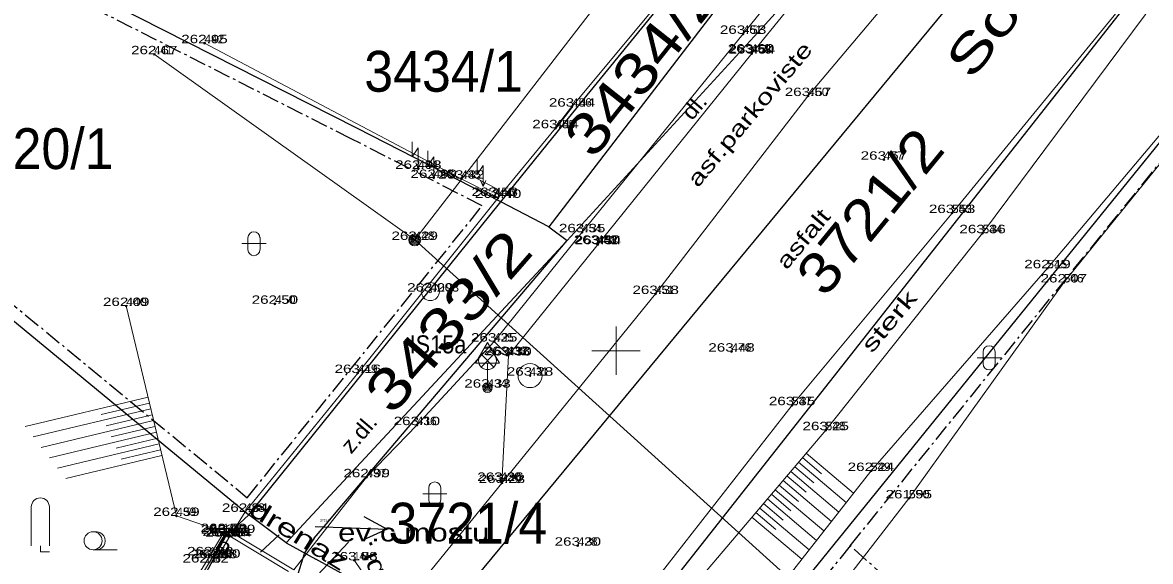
# Model space of a CAD drawing. Extents: x -568530 to -568223, y -1154101 to -1153740.
# Drawn here: x -568424.7 to -568377.75, y -1153908.77 to -1153886.34 of the extents above; entities that cross this region are included whole.
import ezdxf
from ezdxf.enums import TextEntityAlignment as Align

# ---------------------------------------------------------------- set-up
doc = ezdxf.new("R2010")
doc.units = 0
doc.header["$LTSCALE"] = 0.14
doc.header["$PDMODE"] = 32
doc.header["$PDSIZE"] = 0.07
doc.linetypes.add('DOT_DASHED', pattern=[7.7, 5, -1.2, 0.3, -1.2])
for name, color, linetype, lineweight in [('1', 7, 'Continuous', 25), ('10', 7, 'Continuous', 13), ('11', 7, 'Continuous', 13), ('12', 7, 'Continuous', 13), ('14', 7, 'Continuous', 13), ('15', 7, 'Continuous', 13), ('21', 7, 'Continuous', 13), ('22', 7, 'Continuous', 13), ('23', 7, 'Continuous', 13), ('24', 7, 'Continuous', 13), ('25', 7, 'Continuous', 13), ('27', 7, 'Continuous', 13), ('33', 7, 'Continuous', 13), ('34', 7, 'Continuous', 13), ('36', 7, 'Continuous', 13), ('4', 7, 'Continuous', 25), ('42', 7, 'Continuous', 13), ('51', 7, 'Continuous', 13), ('6', 7, 'DOT_DASHED', 25), ('61', 7, 'Continuous', 13), ('7', 7, 'Continuous', 13), ('8', 7, 'Continuous', 35), ('9', 7, 'Continuous', 13)]:
    doc.layers.add(name, color=color, linetype=linetype, lineweight=lineweight)
for name, color, linetype in [('13', 7, 'Continuous'), ('18', 7, 'Continuous'), ('19', 7, 'Continuous'), ('20', 7, 'Continuous'), ('40', 7, 'Continuous'), ('49', 7, 'Continuous')]:
    doc.layers.add(name, color=color, linetype=linetype)

msp = doc.modelspace()

# ---------------------------------------------------------------- linework, layer by layer
at = {"layer": '1'}
for p, q in [((-568432.8, -1153892.39), (-568415.28, -1153906.83)), ((-568402.8, -1153894.84), (-568402.04, -1153895.41)), ((-568413.73, -1153908), (-568402.04, -1153895.41)), ((-568413.73, -1153908), (-568412.5, -1153908.68))]:
    msp.add_line(p, q, dxfattribs=at)
for points in [[(-568412.56, -1153907.8), (-568411.98, -1153907.12), (-568411.65, -1153906.73), (-568402.04, -1153895.41), (-568393.94, -1153886.59), (-568382.28, -1153873.78), (-568334.11, -1153813.06), (-568281.93, -1153748.16)], [(-568397.85, -1153916.62), (-568348.36, -1153855.52), (-568306.73, -1153803.52), (-568266.23, -1153754.08)], [(-568404.79, -1153893.8), (-568410.79, -1153890.73), (-568424.86, -1153883.59), (-568440.41, -1153875.53), (-568467.48, -1153868.69)], [(-568413.73, -1153908), (-568415.28, -1153906.83), (-568404.79, -1153893.8), (-568402.87, -1153891.42), (-568401.2, -1153889.36), (-568395.23, -1153882.04), (-568393.86, -1153883.19), (-568402.8, -1153894.84), (-568404.79, -1153893.8)], [(-568415.28, -1153906.83), (-568416.25, -1153907.73), (-568417.28, -1153909.65), (-568429.7, -1153929.89), (-568430.98, -1153931.64), (-568432.38, -1153933.77), (-568434.43, -1153934.79), (-568436.25, -1153936.74), (-568450.95, -1153952.46)], [(-568412.56, -1153907.8), (-568412.97, -1153908.42), (-568413.31, -1153909.52)], [(-568397.85, -1153916.62), (-568398.69, -1153916.13), (-568401.59, -1153914.63), (-568407.5, -1153911.44), (-568412.5, -1153908.68)]]:
    msp.add_lwpolyline(points, dxfattribs=at)
at = {"layer": '10'}
msp.add_line((-568410.89, -1153908.73), (-568410.6, -1153909.16), dxfattribs=at)
for points in [[(-568341.41, -1153838.94), (-568349.83, -1153849.41), (-568360.25, -1153862.43), (-568369.78, -1153874.42), (-568378.19, -1153884.73), (-568386.01, -1153894.27), (-568392.67, -1153902.27), (-568398.22, -1153909.37), (-568401.79, -1153914.15), (-568403.6, -1153916.28)], [(-568384.23, -1153880.16), (-568392.01, -1153889.4), (-568398.35, -1153897.64), (-568404.75, -1153905.51), (-568410.43, -1153912.49)]]:
    msp.add_lwpolyline(points, dxfattribs=at)
at = {"layer": '11'}
for p, q in [((-568404.48, -1153900.2), (-568405.07, -1153899.62)), ((-568413.418, -1153909.12), (-568410.38, -1153905.27)), ((-568415.98, -1153907.59), (-568415.44, -1153906.71)), ((-568416.33, -1153907.55), (-568416.08, -1153907.72)), ((-568416.08, -1153907.72), (-568415.98, -1153907.59)), ((-568416.08, -1153907.72), (-568413.64, -1153909.2)), ((-568415.98, -1153907.59), (-568413.418, -1153909.12))]:
    msp.add_line(p, q, dxfattribs=at)
for points in [[(-568381.7, -1153869.78), (-568383.21, -1153872.58), (-568387.5, -1153877.91), (-568389.32, -1153880.18), (-568394.71, -1153886.81), (-568401.41, -1153895.07), (-568405.07, -1153899.62), (-568408.29, -1153903.1), (-568410.38, -1153905.27)], [(-568384.23, -1153880.16), (-568388.74, -1153880.73), (-568394.35, -1153887.63), (-568400.75, -1153895.57), (-568404.48, -1153900.2), (-568404.75, -1153905.51)], [(-568377.44, -1153885.3), (-568384.74, -1153895.11), (-568391.27, -1153903.31), (-568397.56, -1153910.73)], [(-568415.44, -1153906.71), (-568410.75, -1153900.93), (-568404.91, -1153893.64)], [(-568416.33, -1153907.55), (-568416.89, -1153908.52), (-568416.73, -1153908.64), (-568416.6, -1153908.62), (-568416.08, -1153907.72)], [(-568416.89, -1153908.52), (-568417.08, -1153908.82), (-568425.43, -1153922.37)]]:
    msp.add_lwpolyline(points, dxfattribs=at)
for p in [(-568394.71, -1153886.81), (-568417.13, -1153887.2), (-568394.38, -1153887.59), (-568419.22, -1153887.66), (-568394.35, -1153887.63), (-568392.01, -1153889.4), (-568401.83, -1153889.84), (-568402.52, -1153890.74), (-568388.85, -1153892.05), (-568408.23, -1153892.43), (-568407.59, -1153892.81), (-568406.44, -1153892.84), (-568405.05, -1153893.56), (-568404.91, -1153893.64), (-568386.01, -1153894.27), (-568401.41, -1153895.07), (-568384.74, -1153895.11), (-568408.38, -1153895.39), (-568400.79, -1153895.55), (-568400.75, -1153895.57), (-568382.04, -1153896.57), (-568381.36, -1153897.16), (-568398.35, -1153897.64), (-568420.39, -1153898.14), (-568414.2, -1153898.05), (-568405.07, -1153899.62), (-568404.54, -1153900.18), (-568404.48, -1153900.2), (-568395.19, -1153900.04), (-568410.75, -1153900.93), (-568403.58, -1153901.04), (-568405.35, -1153901.54), (-568392.67, -1153902.27), (-568408.29, -1153903.1), (-568391.27, -1153903.31), (-568410.38, -1153905.27), (-568404.81, -1153905.42), (-568389.39, -1153905.01), (-568404.75, -1153905.51), (-568387.81, -1153906.15), (-568415.44, -1153906.71), (-568418.3, -1153906.88), (-568416.33, -1153907.55), (-568416.32, -1153907.62), (-568416.25, -1153907.72), (-568416.13, -1153907.74), (-568416.08, -1153907.72), (-568415.98, -1153907.59), (-568401.59, -1153908.12), (-568416.89, -1153908.52), (-568416.73, -1153908.64), (-568416.6, -1153908.62), (-568410.89, -1153908.73)]:
    msp.add_point(p, dxfattribs=at)
at = {"layer": '14'}
for p, q in [((-568420.39, -1153898.14), (-568418.3, -1153906.88)), ((-568418.3, -1153906.88), (-568416.33, -1153907.55))]:
    msp.add_line(p, q, dxfattribs=at)
msp.add_lwpolyline([(-568395.11, -1153912.31), (-568389.39, -1153905.01), (-568382.04, -1153896.57), (-568374.93, -1153888.14), (-568366.7, -1153877.32), (-568357.21, -1153865.06), (-568347.39, -1153851.22), (-568338.19, -1153841.21)], dxfattribs=at)
at = {"layer": '15'}
for p, q in [((-568419.482, -1153901.936), (-568424.601, -1153903.16)), ((-568419.366, -1153902.422), (-568424.262, -1153903.593)), ((-568419.424, -1153902.179), (-568421.427, -1153902.658)), ((-568419.25, -1153902.909), (-568423.923, -1153904.026)), ((-568419.308, -1153902.665), (-568421.222, -1153903.123)), ((-568419.133, -1153903.395), (-568423.584, -1153904.459)), ((-568419.192, -1153903.152), (-568421.016, -1153903.588)), ((-568419.017, -1153903.881), (-568423.245, -1153904.892)), ((-568419.075, -1153903.638), (-568420.811, -1153904.053)), ((-568418.901, -1153904.367), (-568422.906, -1153905.325)), ((-568418.959, -1153904.124), (-568420.606, -1153904.518)), ((-568392.239, -1153904.453), (-568391.45, -1153905.123)), ((-568392.078, -1153904.263), (-568390.111, -1153905.93)), ((-568392.563, -1153904.835), (-568391.767, -1153905.509)), ((-568392.401, -1153904.644), (-568390.419, -1153906.324)), ((-568393.048, -1153905.407), (-568391.037, -1153907.112)), ((-568392.886, -1153905.216), (-568392.085, -1153905.896)), ((-568392.724, -1153905.026), (-568390.728, -1153906.718)), ((-568393.371, -1153905.788), (-568391.345, -1153907.505)), ((-568393.209, -1153905.598), (-568392.402, -1153906.282)), ((-568393.856, -1153906.36), (-568393.037, -1153907.055)), ((-568393.694, -1153906.17), (-568391.654, -1153907.899)), ((-568393.533, -1153905.979), (-568392.719, -1153906.668)), ((-568394.179, -1153906.742), (-568393.354, -1153907.441)), ((-568394.018, -1153906.551), (-568391.963, -1153908.293)), ((-568394.341, -1153906.933), (-568392.271, -1153908.687))]:
    msp.add_line(p, q, dxfattribs=at)
at = {"layer": '21'}
for radius in [0.375, 0.05]:
    msp.add_circle((-568407.73, -1153897.54), radius, dxfattribs=at)
at = {"layer": '23'}
msp.add_lwpolyline([(-568354.04, -1153929.41), (-568364.61, -1153923.44), (-568379.16, -1153915.86), (-568390.37, -1153909.46), (-568387.81, -1153906.15), (-568381.36, -1153897.16), (-568374.28, -1153888.42), (-568365.82, -1153877.84), (-568356.68, -1153865.62), (-568346.38, -1153852.31), (-568338.19, -1153841.21)], dxfattribs=at)
at = {"layer": '24'}
for p, q in [((-568406.302, -1153892.574), (-568406.44, -1153892.84)), ((-568406.302, -1153892.574), (-568404.912, -1153893.294)), ((-568406.44, -1153892.84), (-568405.05, -1153893.56)), ((-568404.912, -1153893.294), (-568405.05, -1153893.56))]:
    msp.add_line(p, q, dxfattribs=at)
for points in [[(-568408.48, -1153891.304), (-568408.48, -1153891.93), (-568408.23, -1153891.555), (-568408.23, -1153892.43)], [(-568407.84, -1153891.684), (-568407.84, -1153892.31), (-568407.59, -1153891.935), (-568407.59, -1153892.81)], [(-568408.34, -1153892.185), (-568408.23, -1153892.43), (-568408.12, -1153892.185)], [(-568405.777, -1153892.039), (-568405.777, -1153892.665), (-568405.527, -1153892.29), (-568405.527, -1153893.165)], [(-568407.7, -1153892.565), (-568407.59, -1153892.81), (-568407.48, -1153892.565)], [(-568405.637, -1153892.92), (-568405.527, -1153893.165), (-568405.417, -1153892.92)]]:
    msp.add_lwpolyline(points, dxfattribs=at)
at = {"layer": '25', "lineweight": 25}
msp.add_line((-568412.52, -1153907.32), (-568409.523, -1153907.435), dxfattribs=at)
msp.add_lwpolyline([(-568410.503, -1153906.898), (-568409.523, -1153907.435), (-568410.541, -1153907.896)], dxfattribs=at)
at = {"layer": '25'}
for radius in [0.25, 0.2, 0.15, 0.1, 0.05]:
    msp.add_circle((-568408.38, -1153895.39), radius, dxfattribs=at)
at = {"layer": '27'}
msp.add_circle((-568403.58, -1153901.04), 0.5, dxfattribs=at)
at = {"layer": '33'}
for p, q in [((-568405.615, -1153900.68), (-568405.085, -1153900.15)), ((-568405.615, -1153900.15), (-568405.085, -1153900.68)), ((-568405.35, -1153900.79), (-568405.35, -1153901.54))]:
    msp.add_line(p, q, dxfattribs=at)
for centre, radius in [((-568405.35, -1153900.415), 0.375), ((-568405.35, -1153901.54), 0.2), ((-568405.35, -1153901.54), 0.1445), ((-568405.35, -1153901.54), 0.0876)]:
    msp.add_circle(centre, radius, dxfattribs=at)
at = {"layer": '34'}
msp.add_line((-568405.35, -1153900.522), (-568405.35, -1153901.54), dxfattribs=at)
msp.add_lwpolyline([(-568405.85, -1153900.522), (-568404.85, -1153900.522), (-568405.35, -1153899.656)], close=True, dxfattribs=at)
at = {"layer": '36'}
for p, q in [((-568415.57, -1153895.544), (-568414.57, -1153895.544)), ((-568415.32, -1153895.294), (-568415.32, -1153895.794)), ((-568414.82, -1153895.294), (-568414.82, -1153895.794)), ((-568384.719, -1153900.048), (-568384.719, -1153900.548)), ((-568384.219, -1153900.048), (-568384.219, -1153900.548)), ((-568384.969, -1153900.298), (-568383.969, -1153900.298)), ((-568407.795, -1153905.712), (-568407.795, -1153906.212)), ((-568407.295, -1153905.712), (-568407.295, -1153906.212)), ((-568408.045, -1153905.962), (-568407.045, -1153905.962)), ((-568424.339, -1153906.504), (-568424.339, -1153908.129)), ((-568423.589, -1153906.504), (-568423.589, -1153908.129)), ((-568421.767, -1153908.291), (-568420.767, -1153908.291))]:
    msp.add_line(p, q, dxfattribs=at)
msp.add_lwpolyline([(-568423.964, -1153908.129), (-568423.964, -1153908.379), (-568423.589, -1153908.379)], dxfattribs=at)
msp.add_circle((-568421.7665, -1153907.9154), 0.375, dxfattribs=at)
for centre, radius, start, end in [((-568415.0713, -1153895.2958), 0.25, 0, 180), ((-568415.0713, -1153895.7958), 0.25, 180, 0), ((-568384.4694, -1153900.0494), 0.25, 0, 180), ((-568384.4694, -1153900.5494), 0.25, 180, 0), ((-568407.5464, -1153905.7134), 0.25, 0, 180), ((-568423.9641, -1153906.5028), 0.375, 0, 180), ((-568407.5464, -1153906.2134), 0.25, 180, 0), ((-568421.6415, -1153907.9154), 0.375, 260.40593, 99.59407)]:
    msp.add_arc(centre, radius, start, end, dxfattribs=at)
at = {"layer": '4'}
for points in [[(-568271.05, -1153741.89), (-568310.68, -1153791.16), (-568343.12, -1153831.47), (-568381.67, -1153880.2), (-568407.5, -1153911.44)], [(-568401.59, -1153914.63), (-568397.99, -1153910.05), (-568332.4, -1153826.72), (-568306.48, -1153794.28), (-568270.78, -1153751.53)]]:
    msp.add_lwpolyline(points, dxfattribs=at)
at = {"layer": '42'}
for p, q in [((-568414.798, -1153908.382), (-568414.018, -1153907.674)), ((-568413.089, -1153910.05), (-568411.133, -1153907.979))]:
    msp.add_line(p, q, dxfattribs=at)
at = {"layer": '51'}
for points in [[(-568408.38, -1153895.39), (-568385.17, -1153865.34), (-568366.46, -1153836.38)], [(-568419.22, -1153887.66), (-568408.38, -1153895.39), (-568389.55, -1153912.42), (-568363.64, -1153930.12), (-568330.76, -1153952.92)]]:
    msp.add_lwpolyline(points, dxfattribs=at)
at = {"layer": '6'}
for p, q in [((-568390.25, -1153908.12), (-568347.97, -1153855.84)), ((-568411.02, -1153891.18), (-568425.09, -1153884.04)), ((-568405.57, -1153893.97), (-568411.02, -1153891.18)), ((-568432.48, -1153892), (-568415.35, -1153906.12)), ((-568415.35, -1153906.12), (-568405.57, -1153893.97)), ((-568390.25, -1153908.12), (-568396.91, -1153916.39))]:
    msp.add_line(p, q, dxfattribs=at)
msp.add_lwpolyline([(-568292.75, -1153788.12), (-568342.85, -1153941.3), (-568385.34, -1153912.52), (-568390.25, -1153908.12)], dxfattribs=at)
at = {"layer": '61'}
for p, q in [((-568400, -1153899), (-568400, -1153901)), ((-568401, -1153900), (-568399, -1153900))]:
    msp.add_line(p, q, dxfattribs=at)
at = {"layer": '7'}
msp.add_line((-568406.44, -1153892.84), (-568417.13, -1153887.2), dxfattribs=at)
for points in [[(-568384, -1153867.91), (-568390.54, -1153875.99), (-568397.75, -1153884.92), (-568401.83, -1153889.84)], [(-568402.52, -1153890.74), (-568404.91, -1153893.64), (-568405.05, -1153893.56)]]:
    msp.add_lwpolyline(points, dxfattribs=at)
at = {"layer": '8'}
msp.add_line((-568402.52, -1153890.74), (-568401.83, -1153889.84), dxfattribs=at)
at = {"layer": '9'}
msp.add_line((-568416.25, -1153907.72), (-568430.85, -1153931.48), dxfattribs=at)

# ---------------------------------------------------------------- texts
at = {"layer": '12'}
for s, width, p in [('263.53', 1.35, (-568394.71, -1153886.81)), ('262.95', 1.35, (-568417.1305, -1153887.2)), ('262.67', 1.35, (-568419.22, -1153887.66)), ('263.60', 1.35, (-568394.3795, -1153887.59)), ('263.54', 1.35, (-568394.35, -1153887.63)), ('263.57', 1.35, (-568392.01, -1153889.4)), ('263.44', 1.35, (-568401.83, -1153889.84)), ('263.44', 1.35, (-568402.52, -1153890.74)), ('263.67', 1.35, (-568388.85, -1153892.05)), ('262.98', 1.35, (-568408.23, -1153892.43)), ('262.99', 1.35, (-568407.59, -1153892.81)), ('263.32', 1.35, (-568406.44, -1153892.84)), ('263.53', 1.35, (-568405.05, -1153893.56)), ('263.40', 1.35, (-568404.9095, -1153893.64)), ('263.53', 1.35, (-568386.01, -1153894.27)), ('263.29', 1.35, (-568408.38, -1153895.39)), ('263.35', 1.35, (-568401.4105, -1153895.07)), ('263.36', 1.35, (-568384.74, -1153895.11)), ('263.40', 1.35, (-568400.7895, -1153895.55)), ('263.34', 1.35, (-568400.75, -1153895.57)), ('262.19', 1.35, (-568382.04, -1153896.57)), ('262.07', 1.35, (-568381.36, -1153897.16)), ('263.38', 1.35, (-568398.35, -1153897.64)), ('262.09', 1.35, (-568420.39, -1153898.14)), ('262.50', 1.35, (-568414.1995, -1153898.05)), ('263.25', 1.35, (-568405.0705, -1153899.62)), ('263.48', 1.35, (-568395.19, -1153900.04)), ('263.33', 1.35, (-568404.54, -1153900.18)), ('263.30', 1.35, (-568404.4795, -1153900.2)), ('263.16', 1.35, (-568410.75, -1153900.93)), ('263.28', 1.35, (-568403.58, -1153901.04)), ('263.33', 1.35, (-568405.35, -1153901.54)), ('263.35', 1.35, (-568392.6705, -1153902.27)), ('263.10', 1.35, (-568408.2895, -1153903.1)), ('263.25', 1.35, (-568391.2705, -1153903.31)), ('262.99', 1.35, (-568410.38, -1153905.27)), ('262.24', 1.35, (-568389.39, -1153905.01)), ('263.26', 1.35, (-568404.81, -1153905.42)), ('263.23', 1.35, (-568404.75, -1153905.51)), ('261.95', 1.35, (-568387.8105, -1153906.15)), ('262.84', 1.35, (-568415.44, -1153906.71)), ('262.59', 1.35, (-568418.3, -1153906.88)), ('262.79', 1.35, (-568416.33, -1153907.55)), ('263.05', 1.35, (-568416.3205, -1153907.62)), ('262.79', 1.35, (-568415.98, -1153907.59)), ('263.05', 1.35, (-568416.2505, -1153907.72)), ('263.04', 1.35, (-568416.13, -1153907.74)), ('262.81', 1.3, (-568416.08, -1153907.72)), ('263.30', 1.35, (-568401.5895, -1153908.12)), ('263.03', 1.35, (-568416.89, -1153908.52)), ('262.82', 1.35, (-568417.08, -1153908.82)), ('262.83', 1.35, (-568416.73, -1153908.64)), ('262.80', 1.35, (-568416.5995, -1153908.62)), ('263.08', 1.35, (-568410.89, -1153908.73))]:
    msp.add_text(s, height=0.35, dxfattribs=dict(at, width=width)).set_placement(p, align=Align.CENTER)
at = {"layer": '13'}
msp.add_text('461', height=0.35, dxfattribs=at).set_placement((-568394.71, -1153886.81))
for s, width, p in [('442', 1.05, (-568417.13, -1153887.2)), ('441', 0.95, (-568419.22, -1153887.66)), ('459', 1.05, (-568394.38, -1153887.59)), ('458', 1.05, (-568394.35, -1153887.63)), ('460', 1.1, (-568392.01, -1153889.4)), ('456', 1.05, (-568401.83, -1153889.84)), ('455', 1.05, (-568402.52, -1153890.74)), ('477', 1.05, (-568388.85, -1153892.05)), ('444', 1.05, (-568408.23, -1153892.43)), ('443', 1.05, (-568407.59, -1153892.81)), ('445', 1.05, (-568406.44, -1153892.84)), ('446', 1.05, (-568405.05, -1153893.56)), ('447', 1.05, (-568404.91, -1153893.64)), ('543', 1.05, (-568386.01, -1153894.27)), ('448', 1.05, (-568408.38, -1153895.39)), ('454', 1.05, (-568401.41, -1153895.07)), ('544', 1.05, (-568384.74, -1153895.11)), ('453', 1.05, (-568400.79, -1153895.55)), ('452', 1.05, (-568400.75, -1153895.57)), ('545', 1.05, (-568382.04, -1153896.57)), ('546', 1.05, (-568381.36, -1153897.16)), ('451', 0.95, (-568398.35, -1153897.64)), ('440', 1.1, (-568420.39, -1153898.14)), ('450', 1.1, (-568414.2, -1153898.05)), ('435', 1.05, (-568405.07, -1153899.62)), ('476', 1.05, (-568395.19, -1153900.04)), ('433', 1.05, (-568404.54, -1153900.18)), ('432', 1.05, (-568404.48, -1153900.2)), ('449', 1.05, (-568410.75, -1153900.93)), ('431', 0.95, (-568403.58, -1153901.04)), ('434', 1.05, (-568405.35, -1153901.54)), ('547', 1.05, (-568392.67, -1153902.27)), ('436', 1.05, (-568408.29, -1153903.1)), ('548', 1.05, (-568391.27, -1153903.31)), ('437', 1.05, (-568410.38, -1153905.27)), ('549', 1.05, (-568389.39, -1153905.01)), ('430', 1.1, (-568404.81, -1153905.42)), ('429', 1.05, (-568404.75, -1153905.51)), ('550', 1.1, (-568387.81, -1153906.15)), ('438', 1.05, (-568415.44, -1153906.71)), ('439', 1.05, (-568418.3, -1153906.88)), ('147', 0.8, (-568416.33, -1153907.55)), ('148', 0.8, (-568416.32, -1153907.62)), ('152', 0.8, (-568415.98, -1153907.59)), ('149', 0.8, (-568416.25, -1153907.72)), ('151', 0.7, (-568416.13, -1153907.74)), ('150', 0.85, (-568416.08, -1153907.72)), ('428', 1.05, (-568401.59, -1153908.12)), ('155', 0.8, (-568416.89, -1153908.52)), ('156', 0.8, (-568417.08, -1153908.82)), ('154', 0.8, (-568416.73, -1153908.64)), ('153', 0.8, (-568416.6, -1153908.62)), ('144', 0.8, (-568410.89, -1153908.73))]:
    msp.add_text(s, height=0.35, dxfattribs=dict(at, width=width)).set_placement(p)
at = {"layer": '18'}
for s, rotation, width, p in [('3434/2', 51.6, 1.25, (-568400.952, -1153892.08)), ('3721/2', 50.7, 1.15, (-568391.308, -1153897.839)), ('3433/2', 48.9, 1.3, (-568409.319, -1153902.738))]:
    msp.add_text(s, height=1.7, rotation=rotation, dxfattribs=dict(at, width=width)).set_placement(p)
at = {"layer": '18', "width": 0.95}
for height, p in [(1.7, (-568409.47, -1153908.03)), (0.1, (-568412.32, -1153907.12))]:
    msp.add_text('3721/4', height=height, dxfattribs=at).set_placement(p)
at = {"layer": '19', "width": 0.95}
msp.add_text('3434/1', height=1.7, dxfattribs=at).set_placement((-568410.48, -1153889.22))
at = {"layer": '20', "width": 0.95}
msp.add_text('920/1', height=1.7, dxfattribs=at).set_placement((-568426.32, -1153892.44))
at = {"layer": '22', "width": 1.35}
msp.add_text('263.29', height=0.35, dxfattribs=at).set_placement((-568407.73, -1153897.54), align=Align.CENTER)
at = {"layer": '23', "width": 1.15}
msp.add_text('4003', height=0.35, dxfattribs=at).set_placement((-568407.73, -1153897.54))
at = {"layer": '40'}
for s, rotation, width, p in [('asf.parkoviste', 50.073, 1.4, (-568396.594, -1153893.243)), ('dl.', 49.573, 1.15, (-568396.84, -1153890.453)), ('asfalt', 50.073, 1.4, (-568392.897, -1153896.666)), ('sterk', 50.073, 1.6, (-568389.351, -1153900.143)), ('z.dl.', 49.573, 1.1, (-568411.025, -1153904.333)), ('b.', 329.358, 1.25, (-568416.754, -1153908.247))]:
    msp.add_text(s, height=0.65, rotation=rotation, dxfattribs=dict(at, width=width)).set_placement(p)
at = {"layer": '42'}
for s, width, p in [('IS15a', 0.9, (-568407.4105, -1153900.113)), ('ev.c.mostu', 1.3, (-568408.418, -1153907.943))]:
    msp.add_text(s, height=0.75, dxfattribs=dict(at, width=width)).set_placement(p, align=Align.CENTER)
for s, rotation, width, p in [('drenaz', 328.215, 1.5, (-568413.4, -1153907.9877)), ('obr.', 113.277, 1.3, (-568409.7808, -1153908.8792))]:
    msp.add_text(s, height=0.75, rotation=rotation, dxfattribs=dict(at, width=width)).set_placement(p, align=Align.CENTER)
at = {"layer": '49', "width": 1.45}
msp.add_text('Sochorova', height=1.5, rotation=52.355, dxfattribs=at).set_placement((-568385.198, -1153888.782))

doc.saveas('drawing.dxf')
